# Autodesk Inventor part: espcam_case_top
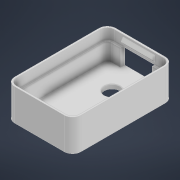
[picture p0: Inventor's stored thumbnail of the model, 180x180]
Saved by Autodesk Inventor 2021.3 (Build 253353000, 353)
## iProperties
Created: 2022-11
Part Number: espcam_case_top
Material: Generisch
Document SubType Name: Modeling
Designer: markus.rampp
Density: 1 g/cm^3
Appearance: Vorgabe
Author: markus.rampp
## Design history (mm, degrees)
sketch "Skizze1"
  geometry: L1 (13.75, -22)-(-13.75, -22); L2 (-13.75, -22)-(-13.75, 22); L3 (-13.75, 22)-(13.75, 22); L4 (13.75, 22)-(13.75, -22); L5 (0, -32.584)-(0, 34.866); L6 (19.267, 0)-(-23.44, 0); 1 further point
  constraints: 12 end point, 2 horizontal, 2 parallel, 2 point on line, 1 perpendicular, 1 vertical, 2 other
  dimensions: "d0" = 27.5 distance of L1.start L1.end; "d1" = 44 distance of L1.end L2.end
extrude "Extrusion1" new body sketch "Skizze1" distance "d2" = 13; taper "d3" = 0 deg
fillet "Rundung1" dims "d19" = 2
feature "Wandung1" dims "d4" = 2
sketch "Skizze2"
  geometry: C1 r 3.75 at (13.75, 32.5); 5 further points; 2 other entities
  constraints: 1 centre point, 2 other
  dimensions: "d5" = 7.5 diameter of C1; "d6" = 13.75 dimension on C1.centre; "d7" = 11.5 dimension on C1.centre
extrude "Extrusion2" cut sketch "Skizze2" extent not by distance; stored distance "d8" = 0; taper "d9" = 0 deg
chamfer "Fase1" distance "d10" = 0.2; stored, may be unused: second distance "d11" = 2, angle "d12" = 45 deg
sketch "Skizze3"
  geometry: L1 (-14.95, -20)-(-14.95, 20); L2 (-11.75, 23.2)-(11.75, 23.2); L3 (14.95, 20)-(14.95, -20); L4 (11.75, -23.2)-(-11.75, -23.2); L5 (13.75, 20)-(13.75, -20) reference; L6 (11.75, -22)-(-11.75, -22) reference; A1 r 3.2 centre (-11.75, 20) between (-11.75, 23.2) and (-14.95, 20); A2 r 3.2 centre (11.75, 20) between (14.95, 20) and (11.75, 23.2); A3 r 2 centre (11.75, 20) between (13.75, 20) and (11.75, 22) reference; A4 r 3.2 centre (11.75, -20) between (11.75, -23.2) and (14.95, -20); A5 r 3.2 centre (-11.75, -20) between (-14.95, -20) and (-11.75, -23.2); 4 further points; 1 other entity
  constraints: 8 end point, 8 point on circle, 8 tangent, 4 centre point, 3 perpendicular, 1 concentric, 1 vertical, 1 other
  dimensions: "d20" = 1.2 dimension on L1; "d21" = 1.2 distance between parallel lines of L5 L3; "d22" = 1.2 distance between parallel lines of L6 L4; "d23" = 3.2 radius of A1; "d24" = 3.2 radius of A5; "d25" = 3.2 radius of A4
extrude "Extrusion3" cut sketch "Skizze3" distance "d17" = 5; taper "d18" = 0 deg
sketch "Skizze4"
  geometry: L1 (13, -23.2)-(8, -23.2) reference; L2 (12, -23.2)-(10.5, -22.2); L3 (10.5, -22.2)-(9, -23.2); L4 (12, -23.2)-(9, -23.2); L5 (8, -20)-(8, -23.2) reference; 1 further point
  constraints: 6 end point, 2 point on line, 1 horizontal
  dimensions: "d26" = 2.5 distance from line of L2.end L5; "d27" = 1 distance from line of L1 L2.end; "d28" = 3 distance of L3.end L2.start; "d29" = 1.5 horizontal distance of L3.end L2.end
extrude "Extrusion4" join sketch "Skizze4" stored distance "d30" = 15; taper "d31" = 0 deg
mirror "Spiegeln1"
sketch "Skizze5"
  geometry: L1 (4.25, 2)-(19.25, 2); L2 (19.25, 2)-(19.25, 10); L3 (19.25, 10)-(4.25, 10); L4 (4.25, 10)-(4.25, 2); L5 (0, 0)-(23.5, 0) reference; 1 further point
  constraints: 8 end point, 2 parallel, 1 horizontal, 1 perpendicular
  dimensions: "d32" = 15 distance of L3.end L2.end; "d33" = 8 distance of L2.end L1.end; "d34" = 7.5 distance from line of point (11.75, 2) L4; "d35" = 2 distance between parallel lines of L5 L1
extrude "SDSlot" cut sketch "Skizze5" distance "d36" = 15; taper "d37" = 0 deg
node "Volumenkörper1"
